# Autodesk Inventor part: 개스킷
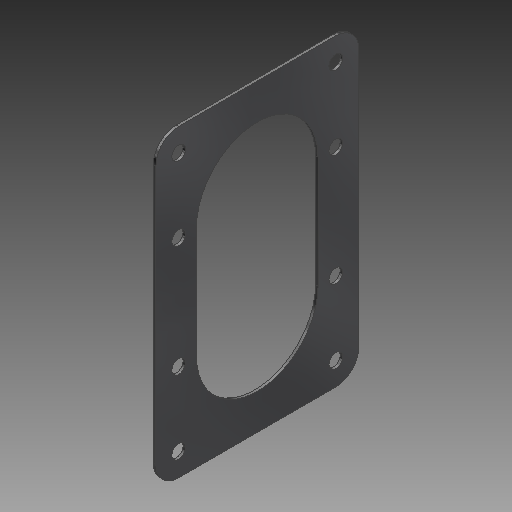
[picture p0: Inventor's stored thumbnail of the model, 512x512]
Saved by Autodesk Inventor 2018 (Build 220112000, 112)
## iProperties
Created: 2019-03
Part Number: 개스킷
Material: 고무
Document SubType Name: Modeling
Designer: mduedu
Density: 1 g/cm^3
Appearance: 고무 - 검은색 - 버전 1.1
Author: mduedu
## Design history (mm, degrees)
sketch "스케치1"
  geometry: L1 (-60, 40)-(60, 40); L2 (60, 40)-(60, -40); L3 (60, -40)-(-60, -40); L4 (-60, -40)-(-60, 40); L5 (-60, 40)-(60, -40); L6 (60, 40)-(-60, -40); 1 further point
  constraints: 12 end point, 2 midpoint, 2 parallel, 1 horizontal, 1 perpendicular
  dimensions: "d21" = 120 distance of L2.end L3.end; "d22" = 80 distance of L1.end L2.end
extrude "돌출1" new body sketch "스케치1" distance "d3" = 1; taper "d4" = 0 deg
fillet "모깎기1" dims "d5" = 9
sketch "스케치2" dims "d6" = 48
  geometry: L1 (-24, -22)-(24, -22); L2 (24, -22)-(24, 22); L3 (24, 22)-(-24, 22); L4 (-24, 22)-(-24, -22); L5 (-24, -22)-(24, 22); L6 (24, -22)-(-24, 22); 3 further points
  constraints: 12 end point, 4 midpoint, 2 horizontal alignment, 2 parallel, 1 horizontal, 1 perpendicular, 4 other
  dimensions: "d8" = 22 distance from line of L3 point (0, 0)
extrude "돌출2" cut sketch "스케치2" extent not by distance; stored distance "d9" = 1; taper "d10" = 0 deg
sketch "스케치3"
  geometry: L1 (-24, -22)-(-24, 22) reference; L2 (24, 22)-(24, -22) reference; L3 (40, -51)-(40, 51) reference; L4 (31, 60)-(-31, 60) reference; L5 (-40, 51)-(-40, -51) reference; L6 (-31, -60)-(31, -60) reference; L7 (-31, 51)-(31, 51); L8 (31, 51)-(31, -51); L9 (31, -51)-(-31, -51); L10 (-31, -51)-(-31, 51); A1 r 24 centre (0, 22) between (24, 22) and (-24, 22) reference; A2 r 24 centre (0, -22) between (-24, -22) and (24, -22) reference; A3 r 9 centre (31, -51) between (31, -60) and (40, -51) reference; A4 r 9 centre (31, 51) between (40, 51) and (31, 60) reference; A5 r 9 centre (-31, 51) between (-31, 60) and (-40, 51) reference; A6 r 9 centre (-31, -51) between (-40, -51) and (-31, -60) reference; 9 further points
  constraints: 8 end point, 4 coincident, 4 horizontal alignment, 4 point on line, 2 parallel, 1 horizontal, 1 perpendicular
  dimensions: "d23" = 102 distance between parallel lines of L9 L7 (derived); "d24" = 29 distance from line of point (-31, 22) L7 (derived); "d25" = 29 distance from line of point (-31, -22) L9 (derived)
hole "구멍1" sketch "스케치3" at (-31, 51), (31, 51), (31, -51), (-31, -51), (-31, -22), (-31, 22), (31, 22), (31, -22) diameter "d14" = 5.5; stored, may be unused: countersink angle "d18" = 90 deg, drill point angle "d20" = 118 deg; dims "d15" = 6, "d16" = 4, "d17" = 2, "d19" = 8
node "솔리드1"
node "투영된 루프1"
